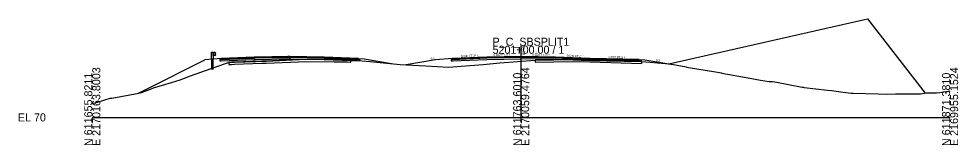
# Model space of a CAD drawing. Extents: x -26 to 1303, y -3010 to 12033.
# Drawn here: x 974.3 to 1302.8, y 2490.3 to 2534.4 of the extents above; entities that cross this region are included whole.
import ezdxf

# ---------------------------------------------------------------- set-up
doc = ezdxf.new("R2010")
doc.units = 0
for name, color, linetype in [('RD_GPK_XS_Cell', 7, 'Continuous'), ('RD_PD_Final_TrvlWay', 7, 'Continuous'), ('RD_Sketch10', 7, 'Continuous'), ('RD_XS_Base', 7, 'Continuous'), ('RD_XS_ExGround', 7, 'Continuous'), ('RD_XS_ExPaveRet', 7, 'Continuous'), ('RD_XS_GR', 7, 'Continuous'), ('RD_XS_Greenside', 7, 'Continuous'), ('RD_XS_Pave', 7, 'Continuous'), ('RD_XS_PaveOvlay_CP', 7, 'Continuous'), ('RD_XS_TieSlope', 7, 'Continuous'), ('RD_XS_TX_Elev_EX', 7, 'Continuous'), ('RD_XS_TX_Elev_PR', 7, 'Continuous'), ('RD_XS_TX_Slope', 7, 'Continuous')]:
    doc.layers.add(name, color=color, linetype=linetype)

msp = doc.modelspace()

# ---------------------------------------------------------------- linework, layer by layer
at = {"layer": 'RD_GPK_XS_Cell'}
for p, q in [((1150, 2500), (1150, 2525)), ((1000, 2500), (1150, 2500)), ((1150, 2500), (1300, 2500))]:
    msp.add_line(p, q, dxfattribs=at)
at = {"layer": 'RD_PD_Final_TrvlWay'}
msp.add_lwpolyline([(1042.23, 2516.73), (1042.23, 2520.33), (1041.73, 2520.29), (1041.73, 2516.73)], dxfattribs=at)
at = {"layer": 'RD_Sketch10'}
msp.add_lwpolyline([(1201.68, 2518.66), (1271.15, 2534.38), (1291.28, 2508.45)], dxfattribs=at)
at = {"layer": 'RD_XS_Base'}
for p, q in [((1045.09, 2520.24), (1044.61, 2520.22)), ((1044.61, 2520.22), (1044.61, 2520.21)), ((1044.61, 2520.21), (1044.61, 2519.72)), ((1045.11, 2520.24), (1045.09, 2520.24)), ((1056.6, 2520.71), (1045.11, 2520.24)), ((1045.11, 2519.74), (1056.6, 2520.21)), ((1057.11, 2520.73), (1056.6, 2520.71)), ((1056.6, 2520.21), (1057.11, 2520.23)), ((1068.45, 2520.95), (1057.11, 2520.73)), ((1057.11, 2520.23), (1068.45, 2520.45)), ((1069.11, 2520.97), (1068.45, 2520.95)), ((1068.45, 2520.45), (1069.11, 2520.47)), ((1069.11, 2521.12), (1069.11, 2521.13)), ((1069.11, 2521.13), (1069.11, 2521.09)), ((1069.11, 2520.97), (1069.11, 2521.13)), ((1069.11, 2521.13), (1069.11, 2521.13)), ((1069.11, 2521.13), (1069.11, 2521.13)), ((1069.11, 2521.13), (1069.11, 2520.47)), ((1069.11, 2520.97), (1069.11, 2521.12)), ((1069.11, 2521.09), (1069.11, 2520.47)), ((1069.11, 2520.94), (1069.11, 2520.97)), ((1069.11, 2520.47), (1069.11, 2520.97)), ((1069.11, 2520.97), (1069.11, 2520.97)), ((1069.11, 2520.97), (1069.11, 2520.97)), ((1069.11, 2520.97), (1069.11, 2520.97)), ((1081.11, 2520.73), (1069.11, 2520.97)), ((1069.11, 2520.47), (1069.11, 2520.94)), ((1069.11, 2520.47), (1069.11, 2520.47)), ((1069.11, 2520.47), (1069.11, 2520.47)), ((1069.11, 2520.47), (1081.11, 2520.23)), ((1093.11, 2520.25), (1081.11, 2520.73)), ((1081.11, 2520.23), (1093.61, 2519.73)), ((1083.11, 2520.65), (1083.11, 2520.65)), ((1083.11, 2520.15), (1083.11, 2520.15)), ((1093.61, 2520.23), (1093.11, 2520.25)), ((1093.11, 2520.25), (1093.11, 2520.25)), ((1093.61, 2519.73), (1093.61, 2520.23)), ((1093.61, 2520.23), (1093.61, 2520.23)), ((1126, 2520.24), (1125.5, 2520.22)), ((1125.5, 2520.22), (1125.5, 2520.22)), ((1125.5, 2520.22), (1125.5, 2519.72)), ((1138, 2520.72), (1126, 2520.24)), ((1126, 2520.24), (1126, 2520.24)), ((1126, 2519.74), (1138, 2520.22)), ((1136, 2520.64), (1136, 2520.64)), ((1136, 2520.14), (1136, 2520.14)), ((1150, 2520.96), (1138, 2520.72)), ((1138, 2520.22), (1150, 2520.46)), ((1150, 2520.46), (1150, 2521.12)), ((1150, 2521.12), (1150, 2521.12)), ((1150, 2521.12), (1150, 2521.12)), ((1150, 2521.12), (1150, 2520.96)), ((1150, 2520.96), (1150, 2520.96)), ((1150, 2520.96), (1162, 2520.72)), ((1150, 2520.96), (1150, 2520.96)), ((1150, 2520.46), (1150, 2520.96)), ((1150, 2520.96), (1150, 2520.96)), ((1150, 2520.96), (1150, 2520.96)), ((1162, 2520.22), (1150, 2520.46)), ((1150, 2520.46), (1150, 2520.46)), ((1150, 2520.46), (1150, 2520.46)), ((1162, 2520.72), (1162, 2520.72)), ((1162, 2520.72), (1174, 2520.24)), ((1174, 2519.74), (1162, 2520.22)), ((1162, 2520.22), (1162, 2520.22)), ((1174, 2520.24), (1174, 2520.24)), ((1174, 2520.24), (1191.3, 2519.9)), ((1191.3, 2519.9), (1191.3, 2519.9)), ((1191.3, 2519.9), (1191.8, 2519.89)), ((1191.8, 2519.89), (1191.8, 2519.89)), ((1191.8, 2519.89), (1191.8, 2519.39)), ((1044.61, 2519.72), (1045.09, 2519.74)), ((1045.09, 2519.74), (1045.11, 2519.74)), ((1125.5, 2519.72), (1126, 2519.74)), ((1191.8, 2519.39), (1174, 2519.74))]:
    msp.add_line(p, q, dxfattribs=at)
at = {"layer": 'RD_XS_ExGround'}
msp.add_lwpolyline([(1000, 2504.79), (1001.89, 2505.35), (1006.23, 2506.75), (1006.8, 2506.7), (1016.28, 2508.42), (1017.23, 2508.73), (1020.42, 2509.8), (1021.4, 2510.35), (1027.72, 2512.16), (1030.77, 2513.1), (1032.27, 2513.66), (1034.32, 2514.47), (1036.04, 2515.12), (1037.09, 2515.48), (1037.27, 2515.49), (1046.65, 2518.75), (1047.79, 2519.2), (1049.74, 2519.28), (1060.77, 2519.66), (1074.72, 2520.27), (1089.21, 2520.08), (1090.4, 2520.07), (1091.5, 2519.99), (1097.21, 2519.44), (1107.63, 2518.49), (1116.58, 2517.97), (1124.7, 2517.53), (1128.97, 2517.86), (1136.73, 2518.5), (1142.51, 2518.98), (1154.95, 2520.01), (1161.37, 2520.12), (1170.31, 2520.22), (1185, 2519.76), (1192.21, 2519.54), (1200.51, 2518.77), (1203.32, 2518.5), (1207.73, 2517.59), (1207.93, 2517.55), (1208.48, 2517.45), (1218, 2515.85), (1220.05, 2515.5), (1220.06, 2515.5), (1220.13, 2515.48), (1229.43, 2513.81), (1233.65, 2512.97), (1236.67, 2512.51), (1237.9, 2512.51), (1238.73, 2512.35), (1248.32, 2510.55), (1248.74, 2510.5), (1249.01, 2510.45), (1257.09, 2509.51), (1258.47, 2509.4), (1262.59, 2508.74), (1265.46, 2508.5), (1266.13, 2508.5), (1274.81, 2508.21), (1278.02, 2508.06), (1280.88, 2508.16), (1289.68, 2508.21), (1291.7, 2508.51), (1294.24, 2508.52), (1295.28, 2508.53), (1296.36, 2508.63), (1297.86, 2508.89), (1300, 2509.22)], dxfattribs=at)
at = {"layer": 'RD_XS_ExPaveRet'}
for points in [[(1090.4, 2520.07), (1090.4, 2520.07), (1089.21, 2520.08), (1084.64, 2520.14), (1074.72, 2520.27), (1072.18, 2520.16), (1060.77, 2519.66), (1059.26, 2519.61), (1049.74, 2519.28), (1048.68, 2519.23), (1047.79, 2519.2), (1047.79, 2519.1), (1047.79, 2518.45), (1048.68, 2518.48), (1049.74, 2518.53), (1059.26, 2518.86), (1060.77, 2518.91), (1072.18, 2519.41), (1074.72, 2519.52), (1084.64, 2519.39), (1089.21, 2519.33), (1090.4, 2519.32), (1090.4, 2519.32), (1090.4, 2519.32), (1090.4, 2519.32), (1090.4, 2519.55), (1090.4, 2520.07), (1090.4, 2520.07), (1090.4, 2520.07)], [(1090.4, 2520.07), (1090.4, 2520.07), (1089.21, 2520.08), (1084.64, 2520.14), (1074.72, 2520.27), (1072.18, 2520.16), (1060.77, 2519.66), (1059.26, 2519.61), (1049.74, 2519.28), (1048.68, 2519.23), (1047.79, 2519.2), (1047.79, 2519.1), (1047.79, 2518.45), (1048.68, 2518.48), (1049.74, 2518.53), (1059.26, 2518.86), (1060.77, 2518.91), (1072.18, 2519.41), (1074.72, 2519.52), (1084.64, 2519.39), (1089.21, 2519.33), (1090.4, 2519.32), (1090.4, 2519.32), (1090.4, 2519.32), (1090.4, 2519.55), (1090.4, 2520.07), (1090.4, 2520.07)], [(1185, 2519.76), (1170.31, 2520.22), (1170.31, 2520.22), (1161.37, 2520.12), (1161.37, 2520.12), (1154.95, 2520.01), (1154.95, 2520.01), (1154.95, 2520.01), (1154.95, 2520.01), (1154.95, 2519.26), (1154.95, 2519.26), (1154.95, 2519.26), (1161.37, 2519.37), (1161.37, 2519.37), (1170.31, 2519.47), (1170.31, 2519.47), (1185, 2519.01), (1185, 2519.01), (1192.21, 2518.79), (1192.21, 2519.54), (1192.21, 2519.54), (1185, 2519.76), (1185, 2519.76)], [(1185, 2519.76), (1170.31, 2520.22), (1161.37, 2520.12), (1154.95, 2520.01), (1154.95, 2519.26), (1161.37, 2519.37), (1170.31, 2519.47), (1185, 2519.01), (1192.21, 2518.79), (1192.21, 2519.54), (1185, 2519.76)]]:
    msp.add_lwpolyline(points, dxfattribs=at)
at = {"layer": 'RD_XS_GR'}
for p, q in [((1041.73, 2520.29), (1041.73, 2522.73)), ((1041.73, 2522.73), (1041.98, 2522.73)), ((1042.23, 2520.33), (1041.73, 2520.29)), ((1041.98, 2522.73), (1042.23, 2522.73)), ((1042.23, 2522.73), (1042.23, 2520.33)), ((1042.23, 2521.56), (1042.23, 2522.73)), ((1042.23, 2522.73), (1042.9, 2522.73)), ((1042.9, 2521.56), (1042.23, 2521.56)), ((1042.9, 2522.73), (1042.9, 2521.56)), ((1042.91, 2522.72), (1042.9, 2522.73)), ((1042.9, 2522.73), (1042.9, 2522.7)), ((1042.9, 2522.7), (1042.9, 2521.56)), ((1042.9, 2522.14), (1043.16, 2522.43)), ((1042.91, 2522.14), (1042.9, 2522.14)), ((1042.9, 2521.56), (1043.16, 2521.84)), ((1043.17, 2522.44), (1042.91, 2522.72)), ((1043.17, 2521.85), (1042.91, 2522.14)), ((1043.16, 2522.43), (1043.17, 2522.44)), ((1043.16, 2521.84), (1043.17, 2521.85))]:
    msp.add_line(p, q, dxfattribs=at)
at = {"layer": 'RD_XS_Greenside'}
for p, q in [((1018.5, 2509.65), (1039.42, 2520.11)), ((1095.11, 2520.4), (1105.38, 2518.69)), ((1120, 2520.08), (1109.73, 2518.37)), ((1193.3, 2520.06), (1201.68, 2518.66)), ((1015.92, 2508.36), (1018.5, 2509.65))]:
    msp.add_line(p, q, dxfattribs=at)
at = {"layer": 'RD_XS_Pave'}
for p, q in [((1056.6, 2521.02), (1045.11, 2520.56)), ((1056.6, 2520.86), (1045.11, 2520.4)), ((1045.11, 2520.4), (1056.6, 2520.86)), ((1045.11, 2520.24), (1056.6, 2520.71)), ((1045.11, 2520.56), (1045.11, 2520.56)), ((1045.11, 2520.56), (1045.11, 2520.4)), ((1045.11, 2520.4), (1045.11, 2520.4)), ((1045.11, 2520.4), (1045.11, 2520.24)), ((1057.11, 2521.04), (1056.6, 2521.02)), ((1057.11, 2520.88), (1056.6, 2520.86)), ((1056.6, 2520.86), (1057.11, 2520.88)), ((1056.6, 2520.71), (1057.11, 2520.73)), ((1068.45, 2521.27), (1057.11, 2521.04)), ((1068.45, 2521.11), (1057.11, 2520.88)), ((1057.11, 2520.88), (1068.45, 2521.11)), ((1057.11, 2520.73), (1068.45, 2520.95)), ((1069.11, 2521.28), (1068.45, 2521.27)), ((1069.11, 2521.13), (1068.45, 2521.11)), ((1068.45, 2521.11), (1069.11, 2521.13)), ((1068.45, 2520.95), (1069.11, 2520.97)), ((1081.11, 2521.04), (1069.11, 2521.28)), ((1069.11, 2521.28), (1069.11, 2521.28)), ((1069.11, 2521.28), (1069.11, 2521.28)), ((1069.11, 2521.12), (1069.11, 2521.13)), ((1069.11, 2521.13), (1069.11, 2521.12)), ((1069.11, 2520.97), (1069.11, 2521.13)), ((1069.11, 2521.13), (1069.11, 2521.13)), ((1069.11, 2521.13), (1069.11, 2521.13)), ((1069.11, 2521.13), (1069.11, 2521.13)), ((1069.11, 2521.13), (1069.11, 2521.13)), ((1069.11, 2521.13), (1081.11, 2520.89)), ((1081.11, 2520.89), (1069.11, 2521.13)), ((1069.11, 2521.13), (1069.11, 2521.13)), ((1069.11, 2521.13), (1069.11, 2521.13)), ((1069.11, 2521.13), (1069.11, 2520.97)), ((1069.11, 2520.97), (1069.11, 2521.12)), ((1069.11, 2521.12), (1069.11, 2520.97)), ((1069.11, 2520.97), (1069.11, 2520.97)), ((1069.11, 2520.97), (1069.11, 2520.97)), ((1069.11, 2520.97), (1081.11, 2520.73)), ((1093.11, 2520.56), (1081.11, 2521.04)), ((1081.11, 2520.89), (1093.11, 2520.41)), ((1093.11, 2520.41), (1081.11, 2520.89)), ((1081.11, 2520.73), (1093.11, 2520.25)), ((1083.11, 2520.96), (1083.11, 2520.96)), ((1083.11, 2520.81), (1083.11, 2520.81)), ((1083.11, 2520.81), (1083.11, 2520.81)), ((1083.11, 2520.65), (1083.11, 2520.65)), ((1093.11, 2520.41), (1093.11, 2520.56)), ((1093.11, 2520.56), (1093.11, 2520.56)), ((1093.11, 2520.25), (1093.11, 2520.41)), ((1093.11, 2520.41), (1093.11, 2520.41)), ((1138, 2521.04), (1126, 2520.56)), ((1138, 2520.88), (1126, 2520.4)), ((1126, 2520.4), (1138, 2520.88)), ((1126, 2520.24), (1138, 2520.72)), ((1126, 2520.56), (1126, 2520.56)), ((1126, 2520.56), (1126, 2520.4)), ((1126, 2520.4), (1126, 2520.4)), ((1126, 2520.4), (1126, 2520.24)), ((1136, 2520.96), (1136, 2520.96)), ((1136, 2520.8), (1136, 2520.8)), ((1136, 2520.8), (1136, 2520.8)), ((1136, 2520.64), (1136, 2520.64)), ((1150, 2521.28), (1138, 2521.04)), ((1150, 2521.12), (1138, 2520.88)), ((1138, 2520.88), (1150, 2521.12)), ((1138, 2520.72), (1150, 2520.96)), ((1162, 2521.04), (1150, 2521.28)), ((1150, 2521.28), (1150, 2521.28)), ((1150, 2521.28), (1150, 2521.28)), ((1150, 2520.96), (1150, 2521.12)), ((1150, 2521.12), (1150, 2521.12)), ((1150, 2521.12), (1150, 2521.12)), ((1150, 2521.12), (1150, 2521.12)), ((1150, 2521.12), (1150, 2521.12)), ((1150, 2521.12), (1162, 2520.88)), ((1162, 2520.88), (1150, 2521.12)), ((1150, 2521.12), (1150, 2521.12)), ((1150, 2521.12), (1150, 2521.12)), ((1150, 2521.12), (1150, 2521.12)), ((1150, 2521.12), (1150, 2520.96)), ((1150, 2520.96), (1150, 2520.96)), ((1150, 2520.96), (1150, 2520.96)), ((1150, 2520.96), (1150, 2520.96)), ((1150, 2520.96), (1162, 2520.72)), ((1174, 2520.56), (1162, 2521.04)), ((1162, 2521.04), (1162, 2521.04)), ((1162, 2520.88), (1162, 2520.88)), ((1162, 2520.88), (1174, 2520.4)), ((1174, 2520.4), (1162, 2520.88)), ((1162, 2520.88), (1162, 2520.88)), ((1162, 2520.72), (1162, 2520.72)), ((1162, 2520.72), (1174, 2520.24)), ((1191.3, 2520.22), (1174, 2520.56)), ((1174, 2520.56), (1174, 2520.56)), ((1174, 2520.4), (1174, 2520.4)), ((1174, 2520.4), (1191.3, 2520.06)), ((1191.3, 2520.06), (1174, 2520.4)), ((1174, 2520.4), (1174, 2520.4)), ((1174, 2520.24), (1191.3, 2519.9)), ((1174, 2520.24), (1174, 2520.24)), ((1191.3, 2520.06), (1191.3, 2520.22)), ((1191.3, 2520.22), (1191.3, 2520.22)), ((1191.3, 2519.9), (1191.3, 2520.06)), ((1191.3, 2520.06), (1191.3, 2520.06))]:
    msp.add_line(p, q, dxfattribs=at)
at = {"layer": 'RD_XS_PaveOvlay_CP'}
for p, q in [((1045.11, 2520.56), (1057.11, 2521.04)), ((1057.11, 2521.04), (1069.11, 2521.28)), ((1069.11, 2521.28), (1081.11, 2521.04)), ((1081.11, 2521.04), (1093.11, 2520.56)), ((1138, 2521.04), (1126, 2520.56)), ((1136, 2520.96), (1136, 2520.96)), ((1150, 2521.28), (1138, 2521.04)), ((1162, 2521.04), (1150, 2521.28)), ((1150, 2521.28), (1150, 2521.28)), ((1150, 2521.28), (1150, 2521.28)), ((1174, 2520.56), (1162, 2521.04)), ((1162, 2521.04), (1162, 2521.04)), ((1191.3, 2520.22), (1174, 2520.56)), ((1174, 2520.56), (1174, 2520.56))]:
    msp.add_line(p, q, dxfattribs=at)
at = {"layer": 'RD_XS_TieSlope'}
for p, q in [((1045.11, 2520.56), (1039.42, 2520.11)), ((1093.11, 2520.56), (1095.11, 2520.4)), ((1126, 2520.56), (1120, 2520.08)), ((1191.3, 2520.22), (1193.3, 2520.06))]:
    msp.add_line(p, q, dxfattribs=at)

# ---------------------------------------------------------------- texts
at = {"layer": 'RD_GPK_XS_Cell'}
for s, p in [('P_C_SBSPLIT1', (1140, 2525)), ('5201+00.00 / 1', (1140, 2522.2)), ('EL 70', (974, 2498.6))]:
    msp.add_text(s, height=2.8, dxfattribs=at).set_placement(p)
for s, p in [('E 2170163.8003', (1002.8, 2490)), ('E 2170059.4764', (1152.8, 2490)), ('E 2169955.1524', (1302.8, 2490)), ('N 611655.8211', (1000, 2490)), ('N 611763.6010', (1150, 2490)), ('N 611871.3810', (1300, 2490))]:
    msp.add_text(s, height=2.8, rotation=90, dxfattribs=at).set_placement(p)
at = {"layer": 'RD_XS_TX_Elev_EX'}
msp.add_text('89.60', height=0.6, rotation=90, dxfattribs=at).set_placement((1149.59, 2522.18))
at = {"layer": 'RD_XS_TX_Elev_PR'}
msp.add_text('91.28', height=1, rotation=90, dxfattribs=at).set_placement((1151.21, 2521.72))
at = {"layer": 'RD_XS_TX_Slope'}
for s, rotation, p in [('6:1', 9.4642, (1118.41, 2520.05)), ('0.040 FT./FT.', 2.2906, (1128.93, 2520.95)), ('0.020 FT./FT.', 1.1458, (1140.27, 2521.43)), ('0.020 FT./FT.', 358.8542, (1153.94, 2521.48)), ('0.040 FT./FT.', 357.7094, (1165.94, 2521.16)), ('0.020 FT./FT.', 358.8542, (1180.59, 2520.7)), ('6:1', 350.5377, (1197.14, 2519.65))]:
    msp.add_text(s, height=0.75, rotation=rotation, dxfattribs=at).set_placement(p)

doc.saveas('drawing.dxf')
